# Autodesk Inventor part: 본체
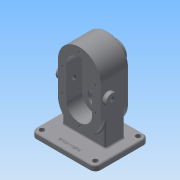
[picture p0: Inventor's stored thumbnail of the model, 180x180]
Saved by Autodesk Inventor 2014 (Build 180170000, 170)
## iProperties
Created: 2020-09
Part Number: 본체
Material: 일반
Document SubType Name: Modeling
Designer: NET
Density: 1 g/cm^3
Appearance: 기본값
Author: NET
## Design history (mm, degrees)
sketch "스케치1"
  geometry: L1 (40, 0)-(-40, 0); L2 (40, 0)-(40, 29.174); L3 (-40, 29.174)-(-40, 0); L4 (-40, -29.174)-(-40, 0); L5 (40, 0)-(40, -29.174); A1 r 40 centre (0, 29.174) between (40, 29.174) and (-40, 29.174); A2 r 40 centre (0, -29.174) between (-40, -29.174) and (40, -29.174); 2 further points
  constraints: 10 end point, 4 point on circle, 3 symmetric about line, 2 centre point, 1 coincident, 1 horizontal, 1 midpoint, 1 parallel, 1 perpendicular, 1 other
  dimensions: "d0" = 80 distance of L1.start L1.end
extrude "돌출1" new body sketch "스케치1" distance "d1" = 53; taper "d2" = 0 deg
node "작업 평면1"
sketch "스케치2"
  geometry: L1 (40, 53)-(-40, 53) reference; L2 (-40, 0)-(-40, 53) reference; L3 (40, 0)-(-40, 0) reference; L4 (40, -30)-(-40, -30); L5 (-40, 70)-(40, 70); L6 (40, 70)-(40, 70); L7 (-40, 26.5)-(40, 26.5); L8 (-40, 70)-(-60, 70); L9 (-60, 70)-(-60, -30); L10 (-60, -30)-(-40, -30); L11 (40, 70)-(60, 70); L12 (60, 70)-(60, -30); L13 (60, -30)-(40, -30); 2 further points
  constraints: 21 end point, 4 parallel, 2 perpendicular, 1 point on line
extrude "돌출2" join sketch "스케치2" distance "d8" = 10; taper "d9" = 0 deg
sketch "스케치3"
  geometry: L1 (-40, 70)-(-40, -30) reference; L2 (40, -30)-(40, 70) reference; L3 (60, 70)-(-60, 70) reference; L4 (-40, 45)-(40, 45); L5 (40, 45)-(40, 8); L6 (40, 8)-(-40, 8); L7 (-40, 8)-(-40, 45); 1 further point
  constraints: 8 end point, 2 parallel, 2 point on line, 1 horizontal, 1 perpendicular
  dimensions: "d10" = 25 distance between parallel lines of L4 L3; "d11" = 37 distance between parallel lines of L6 L4
extrude "돌출3" join sketch "스케치3" stored distance "d12" = 10; taper "d13" = 0 deg
sketch "스케치4"
  geometry: L1 (-24, 29.174)-(-24, -29.174); L2 (24, -29.174)-(24, 29.174); A1 r 40 centre (0, -29.174) between (-40, -29.174) and (40, -29.174) reference; A2 r 40 centre (0, 29.174) between (40, 29.174) and (-40, 29.174) reference; A3 r 24 centre (0, 29.174) between (24, 29.174) and (-24, 29.174); A4 r 24 centre (0, -29.174) between (-24, -29.174) and (24, -29.174); 1 further point
  constraints: 4 end point, 4 point on circle, 3 tangent, 2 centre point, 2 coincident
  dimensions: "d14" = 48 diameter of A3; "d15" = 48 diameter of A4
extrude "돌출4" cut sketch "스케치4" distance "d16" = 29; taper "d17" = 0 deg
sketch "스케치5"
  geometry: C1 r 12.5 at (0, 29.174); C2 r 12.5 at (0, -29.174); A1 r 24 centre (0, 29.174) between (24, 29.174) and (-24, 29.174) reference; A2 r 24 centre (0, -29.174) between (-24, -29.174) and (24, -29.174) reference; 1 further point
  constraints: 2 centre point, 2 coincident
  dimensions: "d18" = 25 diameter of C1; "d19" = 25 diameter of C2
extrude "돌출5" cut sketch "스케치5" distance "d20" = 15; taper "d21" = 0 deg
sketch "스케치6"
  geometry: C1 r 19 at (0, -29.174); A1 r 40 centre (0, -29.174) between (-40, -29.174) and (40, -29.174) reference; 1 further point
  constraints: 1 centre point, 1 coincident
  dimensions: "d22" = 38 diameter of C1
extrude "돌출6" join sketch "스케치6" distance "d23" = 17; taper "d24" = 0 deg
sketch "스케치7"
  geometry: C1 r 19 at (0, 0) reference; C2 r 14 at (0, 0); 1 further point
  constraints: 1 centre point, 1 coincident
  dimensions: "d25" = 28 diameter of C2
extrude "돌출7" cut sketch "스케치7" distance "d26" = 7.3; taper "d27" = 0 deg
sketch "스케치8"
  geometry: C1 r 14 at (0, 0) reference; C2 r 8.5 at (0, 0); 1 further point
  constraints: 1 centre point, 1 coincident
  dimensions: "d28" = 17 diameter of C2
extrude "돌출8" cut sketch "스케치8" stored distance "d29" = 7.3; taper "d30" = 0 deg
chamfer "모따기1" distance "d31" = 1; stored, may be unused: second distance "d32" = 2, angle "d33" = 45 deg
sketch "스케치10"
  geometry: L1 (45, -69.174)-(45, -80) reference; L2 (45, -80)-(70, -80) reference; L3 (70, -80)-(70, -90) reference; L4 (70, -90)-(-30, -90) reference; L5 (-30, -90)-(-30, -80) reference; L6 (-30, -80)-(8, -80) reference; L7 (8, -80)-(8, -69.174) reference; L8 (8, -69.174)-(0, -69.174) reference; L9 (0, -69.174)-(0, -53.174) reference; L10 (0, -53.174)-(29, -53.174) reference; L11 (29, -53.174)-(29, -42.674) reference; L12 (29, -42.674)-(30, -41.674) reference; L13 (30, -41.674)-(44, -41.674) reference; L14 (44, -41.674)-(44, -16.674) reference; L15 (44, -16.674)-(30, -16.674) reference; L16 (30, -16.674)-(29, -15.674) reference; L17 (29, -15.674)-(29, 15.674) reference; L18 (29, 15.674)-(30, 16.674) reference; L19 (30, 16.674)-(44, 16.674) reference; L20 (44, 16.674)-(44, 20.674) reference; L21 (44, 20.674)-(62.7, 20.674) reference; L22 (62.7, 20.674)-(62.7, 15.174) reference; L23 (62.7, 15.174)-(70, 15.174) reference; L24 (70, 15.174)-(70, 10.174) reference; L25 (70, 10.174)-(53, 10.174) reference; L26 (53, 10.174)-(53, -69.174) reference; L27 (53, -69.174)-(45, -69.174) reference; L28 (0, 69.174)-(53, 69.174) reference; L29 (53, 69.174)-(53, 48.174) reference; L30 (53, 48.174)-(70, 48.174) reference; L31 (70, 48.174)-(70, 43.174) reference; L32 (70, 43.174)-(62.7, 43.174) reference; L33 (62.7, 43.174)-(62.7, 37.674) reference; L34 (62.7, 37.674)-(44, 37.674) reference; L35 (44, 37.674)-(44, 41.674) reference; L36 (44, 41.674)-(30, 41.674) reference; L37 (30, 41.674)-(29, 42.674) reference; L38 (29, 42.674)-(29, 53.174) reference; L39 (29, 53.174)-(0, 53.174) reference; L40 (0, 53.174)-(0, 69.174) reference; L41 (69.3, 43.174)-(70, 43.578); 1 further point
  constraints: 2 end point, 2 point on line
  dimensions: "d34" = 30 deg angle of L32 L41; "d35" = 0.7 distance from line of L31 L41.start
  node "절단 모서리 투영1"
fillet "모깎기1" dims "d36" = 0.5
sketch "스케치14"
  geometry: L1 (-31, 22)-(31, -22); L2 (31, 22)-(-31, -22); 5 further points
  constraints: 4 coincident, 4 end point, 2 midpoint
hole "구멍2" sketch "스케치14" at (-31, 22), (31, 22), (31, -22), (-31, -22) diameter "d56" = 4.134; stored, may be unused: countersink angle "d60" = 90 deg, drill point angle "d62" = 118 deg; dims "d57" = 10, "d58" = 4, "d59" = 2, "d61" = 12
sketch "스케치15"
  geometry: C1 r 1.844 at (0, 60.174) reference; 1 further point
hole "구멍3" sketch "스케치15" at (0, 60.174) diameter "d63" = 4.134; stored, may be unused: countersink angle "d67" = 90 deg, drill point angle "d69" = 118 deg; dims "d64" = 10, "d65" = 4, "d66" = 2, "d68" = 12
sketch "스케치16"
  geometry: L1 (0, 0)-(58.348, 0) reference; L2 (119.174, -20)-(119.174, 60) reference; C1 r 11 at (29.174, 14); 2 further points
  constraints: 1 centre point, 1 coincident
  dimensions: "d70" = 90 distance from line of L2 point (29.174, 14); "d71" = 14 distance from line of L1 point (29.174, 14); "d72" = 22 diameter of C1
extrude "돌출11" join sketch "스케치16" distance "d73" = 7.1; taper "d74" = 0 deg
sketch "스케치17"
  geometry: C1 r 11 at (0, 0) reference; 2 further points
  constraints: 1 coincident
hole "구멍4" sketch "스케치17" at (0, 0) diameter "d75" = 8.376; stored, may be unused: countersink angle "d79" = 90 deg, drill point angle "d81" = 118 deg; dims "d76" = 10, "d77" = 4, "d78" = 2, "d80" = 30
fillet "모깎기3" dims "d85" = 10
sketch "스케치18"
  geometry: C1 r 4.5 at (50, -20); C2 r 4.5 at (50, 60); C3 r 4.5 at (-50, 60); C4 r 4.5 at (-50, -20); A1 r 10 centre (-50, 60) between (-50, 70) and (-60, 60) reference; A2 r 10 centre (-50, -20) between (-60, -20) and (-50, -30) reference; A3 r 10 centre (50, -20) between (50, -30) and (60, -20) reference; A4 r 10 centre (50, 60) between (60, 60) and (50, 70) reference; 1 further point
  constraints: 4 centre point, 4 coincident
  dimensions: "d87" = 9 diameter of C1; "d88" = 9 diameter of C2; "d89" = 9 diameter of C3; "d90" = 9 diameter of C4
extrude "돌출12" cut sketch "스케치18" stored distance "d91" = 7.1; taper "d92" = 0 deg
node "작업 평면2"
sketch "스케치19"
  geometry: L1 (50, -30)-(-50, -30) reference; L2 (60, -20)-(60, 60) reference; 2 further points
  constraints: 1 other
  dimensions: "d94" = 12 distance from line of L1 point (0, -18); "d95" = 60 distance from line of L2 point (0, -18)
feature "엠보싱1" sketch "스케치19" dims "d96" = 0.5, "d97" = 0
sketch "스케치20"
  geometry: L1 (70, 43.174)-(62.7, 43.174) reference; L2 (62.7, 15.174)-(70, 15.174) reference; L3 (69.324, 43.174)-(69.324, 15.174); L4 (69.324, 15.174)-(70.411, 14.546); 1 further point
  constraints: 4 end point, 2 point on line, 1 perpendicular
  dimensions: "d98" = 30 deg angle of L2 L4
chamfer "모따기2" distance "d99" = 0.7; stored, may be unused: second distance "d100" = 2, angle "d101" = 30 deg
fillet "모깎기4" dims "d102" = 3
fillet "모깎기5" dims "d103" = 3
node "솔리드1"
mirror "대칭1"
mirror "대칭2"
